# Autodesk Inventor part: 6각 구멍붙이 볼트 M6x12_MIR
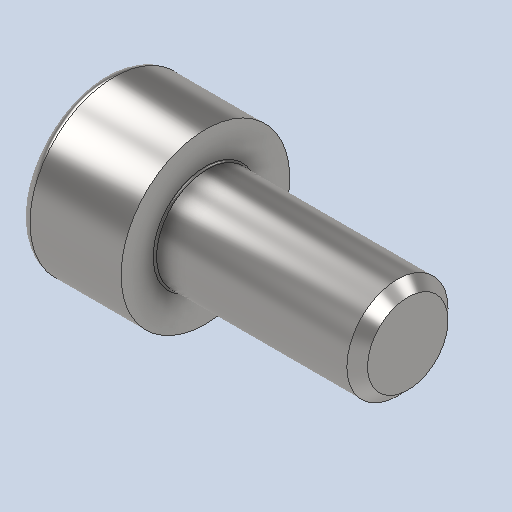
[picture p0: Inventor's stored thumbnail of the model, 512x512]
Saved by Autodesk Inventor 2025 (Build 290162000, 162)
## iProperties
Created: 2026-01
Part Number: 6각 구멍붙이 볼트 M6x12_MIR
Material: 강철, 연강
Description: 6각머리 태핑 나사
Document SubType Name: Modeling
Designer: KDI
Density: 7.85 g/cm^3
Appearance: 기본값
Author: jhkim
Sending System: Autodesk Inventor 2026
Preprocessor: ST-DEVELOPER v20.1
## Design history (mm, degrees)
derived "6각 구멍붙이 볼트 M6x12.ipt"
feature "솔리드1::6각 구멍붙이 볼트 M6x12.ipt" dims "d0" = 10
tag "피쳐 태그1"
node "솔리드1"
